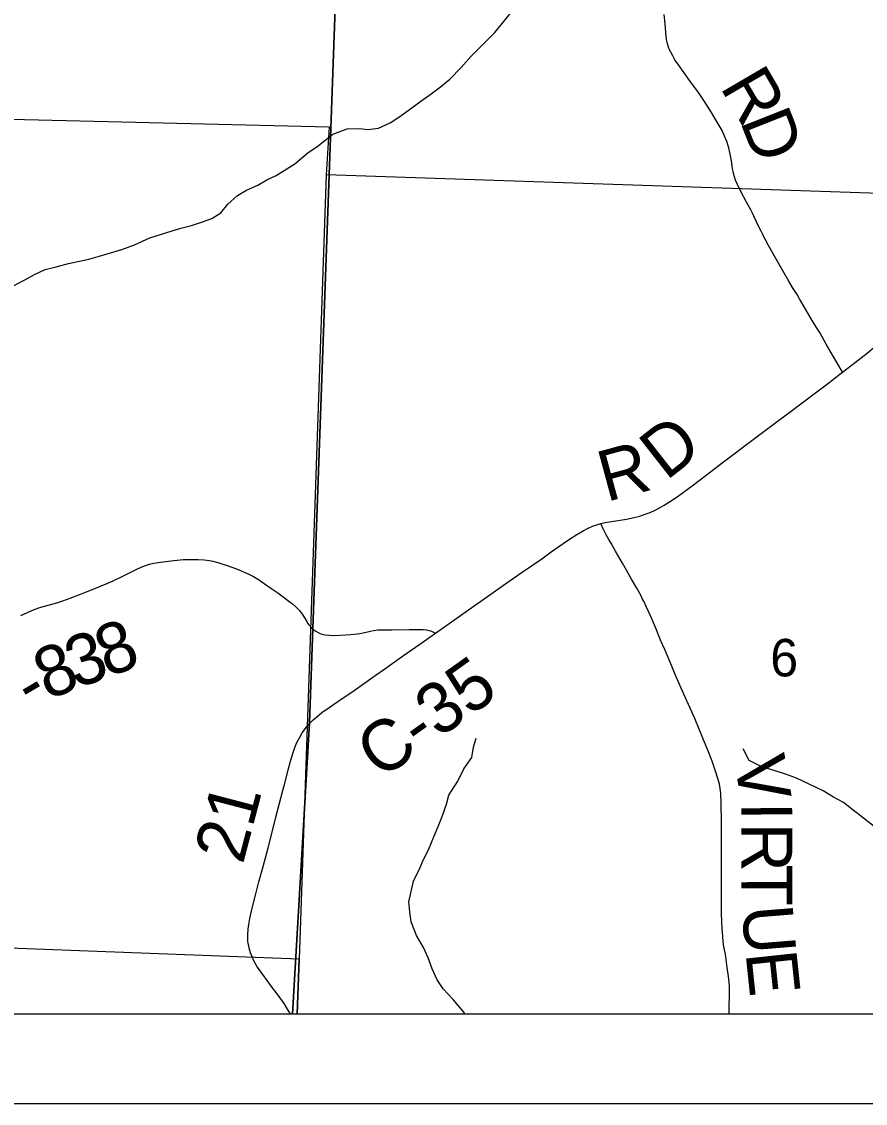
# Model space of a CAD drawing. Extents: x -14196 to 143, y -6096 to 28.
# Drawn here: x 62.009 to 62.952, y 16.799 to 18.007 of the extents above; entities that cross this region are included whole.
import ezdxf

# ---------------------------------------------------------------- set-up
doc = ezdxf.new("R2010")
doc.units = 0
for name, color, linetype in [('GM_X_Corporation', 7, 'Continuous'), ('GM_X_County_Road', 7, 'Continuous'), ('GM_X_County_Road_Text', 7, 'Continuous'), ('GM_X_Minor_River', 7, 'Continuous'), ('GM_X_Section_Text', 7, 'Continuous'), ('GM_X_Township_Road', 7, 'Continuous'), ('GM_X_Township_Road_Text', 7, 'Continuous'), ('SH_Data', 7, 'Continuous')]:
    doc.layers.add(name, color=color, linetype=linetype)

msp = doc.modelspace()

# ---------------------------------------------------------------- linework, layer by layer
at = {"layer": 'GM_X_Corporation'}
for points in [[(58.1028, 16.8985), (62.3117, 16.8985), (62.3309, 17.2239), (62.3347, 17.3291), (62.3753, 18.4575)], [(62.3753, 18.4575), (62.3347, 17.3291), (62.3309, 17.2239), (62.3117, 16.8985), (64.9028, 16.8985)], [(58.1028, 16.8985), (64.9028, 16.8985)]]:
    msp.add_lwpolyline(points, dxfattribs=at)
for points in [[(62.3528, 17.8898), (62.3495, 17.8363), (62.3192, 16.9598), (61.7888, 16.9797), (61.3, 16.9769), (61.3312, 17.9144)], [(62.3171, 16.8985), (63.3498, 16.8985), (63.3993, 17.801), (62.3495, 17.8363), (62.3192, 16.9598)], [(61.2982, 16.8985), (62.3171, 16.8985), (62.3192, 16.9598), (61.7888, 16.9797), (61.3, 16.9769)]]:
    msp.add_lwpolyline(points, close=True, dxfattribs=at)
at = {"layer": 'GM_X_County_Road'}
for points in [[(62.9266, 17.6158), (62.9412, 17.627), (62.9539, 17.6369), (62.962, 17.6437), (62.9685, 17.6497), (62.9741, 17.6555), (62.979, 17.6612), (62.9834, 17.6673), (62.987, 17.6732), (62.9901, 17.6794), (62.9922, 17.6842)], [(62.6563, 17.4465), (62.6614, 17.4476), (62.6708, 17.4493), (62.6852, 17.4516), (62.6938, 17.4532), (62.6999, 17.4549), (62.706, 17.4569), (62.7115, 17.459), (62.7171, 17.4616), (62.722, 17.4642), (62.7272, 17.4672), (62.7362, 17.4728), (62.7434, 17.4777), (62.7585, 17.4887), (62.7742, 17.5008), (62.7921, 17.5143), (62.8283, 17.5416), (62.8417, 17.5516), (62.8566, 17.5629), (62.869, 17.5722), (62.8799, 17.5804), (62.8992, 17.595), (62.9111, 17.604), (62.9234, 17.6134), (62.9266, 17.6158)], [(62.4715, 17.324), (62.4958, 17.3411), (62.5187, 17.3571), (62.5298, 17.365), (62.5476, 17.3776), (62.5675, 17.3914), (62.5905, 17.4073), (62.6011, 17.4148), (62.6204, 17.4284), (62.6298, 17.4344), (62.6367, 17.4385), (62.6422, 17.4413), (62.6471, 17.4435), (62.6518, 17.4452), (62.6563, 17.4465)], [(62.3311, 17.2233), (62.3323, 17.2246), (62.3349, 17.227), (62.339, 17.2306), (62.3448, 17.2352), (62.3539, 17.2417), (62.3662, 17.2501), (62.378, 17.2582), (62.4044, 17.2768), (62.4151, 17.2843), (62.4348, 17.2983), (62.4541, 17.3119), (62.4715, 17.324)], [(62.3096, 16.8985), (62.309, 16.8997), (62.3064, 16.9039), (62.3024, 16.9102), (62.2959, 16.9194), (62.2872, 16.9307), (62.2749, 16.9476), (62.2723, 16.9513), (62.2687, 16.9578), (62.267, 16.9617), (62.265, 16.9668), (62.2642, 16.9695), (62.2636, 16.9719), (62.263, 16.9745), (62.2624, 16.9773), (62.2621, 16.98), (62.2619, 16.9824), (62.2619, 16.9848), (62.262, 16.9873), (62.2624, 16.9934), (62.263, 16.9983), (62.264, 17.005), (62.2663, 17.0152), (62.2704, 17.0313), (62.2744, 17.0463), (62.2789, 17.0631), (62.2846, 17.0841), (62.2882, 17.0986), (62.2933, 17.1184), (62.3015, 17.1496), (62.3032, 17.1562), (62.3071, 17.1712), (62.3095, 17.1808), (62.3121, 17.1897), (62.3143, 17.1961), (62.3167, 17.2018), (62.3195, 17.2072), (62.3227, 17.2125), (62.3263, 17.2174), (62.3283, 17.22), (62.3302, 17.2223), (62.3311, 17.2233)]]:
    msp.add_lwpolyline(points, dxfattribs=at)
at = {"layer": 'GM_X_Minor_River'}
for points in [[(61.9984, 17.7113), (62.0127, 17.719), (62.0236, 17.7248), (62.0353, 17.7305), (62.0478, 17.7333), (62.0614, 17.7372), (62.0841, 17.7422), (62.0947, 17.745), (62.1049, 17.7481), (62.1211, 17.7527), (62.1351, 17.7581), (62.1524, 17.7658), (62.1713, 17.7717), (62.1872, 17.7767), (62.1989, 17.7798), (62.2114, 17.7837), (62.2216, 17.7876), (62.2317, 17.7937), (62.2396, 17.8036), (62.2505, 17.8132), (62.2603, 17.8193), (62.2731, 17.8247), (62.2833, 17.8308), (62.2935, 17.8354), (62.3146, 17.8485), (62.3293, 17.8611), (62.339, 17.8676), (62.3571, 17.8818), (62.373, 17.8876), (62.3866, 17.888), (62.3961, 17.887), (62.4078, 17.8886), (62.421, 17.8944), (62.4308, 17.9009), (62.4413, 17.9081), (62.4526, 17.9169), (62.4669, 17.9269), (62.4771, 17.9346), (62.4876, 17.9433), (62.5004, 17.9563), (62.5117, 17.9689), (62.5233, 17.9808), (62.5379, 17.9953), (62.5481, 18.0075), (62.5556, 18.017)], [(62.5045, 16.8985), (62.5032, 16.9004), (62.4913, 16.9147), (62.4802, 16.9267), (62.4737, 16.9365), (62.4679, 16.9489), (62.4633, 16.961), (62.4583, 16.9727), (62.4506, 16.9862), (62.4444, 17.0013), (62.4428, 17.0126), (62.4419, 17.0236), (62.447, 17.0467), (62.4541, 17.0615), (62.4582, 17.0709), (62.4638, 17.082), (62.4705, 17.0983), (62.4745, 17.1081), (62.479, 17.1191), (62.4838, 17.1328), (62.4867, 17.143), (62.4968, 17.1586), (62.5035, 17.1726), (62.5121, 17.1852), (62.5143, 17.1965), (62.5172, 17.2068)], [(62.9775, 17.0956), (62.9501, 17.1173), (62.9383, 17.1263), (62.9276, 17.1349), (62.9166, 17.1409), (62.9048, 17.148), (62.8892, 17.1551), (62.8751, 17.1618), (62.863, 17.1666), (62.85, 17.1706), (62.8364, 17.1747), (62.8223, 17.1818), (62.8154, 17.1946)]]:
    msp.add_lwpolyline(points, dxfattribs=at)
at = {"layer": 'GM_X_Township_Road'}
for points in [[(62.9266, 17.6158), (62.9249, 17.6185), (62.9197, 17.6272), (62.9159, 17.6336), (62.9082, 17.647), (62.901, 17.66), (62.8974, 17.6658), (62.8939, 17.6716), (62.8785, 17.6978), (62.8757, 17.7026), (62.8706, 17.7104), (62.8664, 17.7173), (62.8609, 17.727), (62.8521, 17.7427), (62.8439, 17.7573), (62.84, 17.7644), (62.8386, 17.7671), (62.837, 17.7705), (62.8356, 17.7733), (62.8331, 17.7783), (62.8277, 17.7894), (62.8258, 17.7933), (62.8247, 17.7955), (62.8239, 17.7972), (62.8208, 17.8031), (62.8194, 17.8056), (62.8128, 17.8177), (62.809, 17.8254), (62.8069, 17.8304), (62.8058, 17.8339), (62.8047, 17.838), (62.8037, 17.8435), (62.8024, 17.852), (62.8011, 17.8593), (62.7993, 17.8666), (62.7971, 17.8737), (62.7948, 17.8795), (62.7919, 17.8857), (62.7877, 17.8933), (62.78, 17.9061), (62.7724, 17.9181), (62.7654, 17.9284), (62.756, 17.9415), (62.7432, 17.9591), (62.7393, 17.9647), (62.7369, 17.9691), (62.7345, 17.9734), (62.7331, 17.9761), (62.7319, 17.979), (62.7309, 17.9826), (62.73, 17.9874), (62.7291, 17.9954), (62.7283, 18.0052), (62.7271, 18.0156)], [(62.6563, 17.4465), (62.6614, 17.4476), (62.6708, 17.4493), (62.6852, 17.4516), (62.6938, 17.4532), (62.6999, 17.4549), (62.706, 17.4569), (62.7115, 17.459), (62.7171, 17.4616), (62.722, 17.4642), (62.7272, 17.4672), (62.7362, 17.4728), (62.7434, 17.4777), (62.7585, 17.4887), (62.7742, 17.5008), (62.7921, 17.5143), (62.8283, 17.5416), (62.8417, 17.5516), (62.8566, 17.5629), (62.869, 17.5722), (62.8799, 17.5804), (62.8992, 17.595), (62.9111, 17.604), (62.9234, 17.6134), (62.9266, 17.6158)], [(62.8, 16.8985), (62.8, 16.9029), (62.8003, 16.9236), (62.8001, 16.9288), (62.7997, 16.9341), (62.7991, 16.9403), (62.7977, 16.9502), (62.7956, 16.9651), (62.794, 16.9734), (62.7932, 16.979), (62.7926, 16.9854), (62.792, 16.9941), (62.7914, 17.0102), (62.7912, 17.0306), (62.7912, 17.038), (62.7912, 17.0454), (62.7912, 17.0631), (62.7913, 17.0786), (62.7913, 17.0949), (62.7913, 17.1125), (62.7909, 17.1341), (62.7904, 17.1447), (62.7898, 17.1504), (62.7889, 17.1551), (62.7873, 17.1617), (62.7851, 17.1688), (62.7808, 17.181), (62.776, 17.1931), (62.7713, 17.2047), (62.7614, 17.2288), (62.7563, 17.2401), (62.7492, 17.256), (62.7407, 17.2753), (62.7346, 17.2896), (62.7278, 17.3056), (62.7233, 17.3164), (62.7185, 17.3278), (62.7123, 17.3427), (62.7072, 17.354), (62.7048, 17.359), (62.7028, 17.3629), (62.7014, 17.3656), (62.6966, 17.3743), (62.6907, 17.3845), (62.6855, 17.3937), (62.6805, 17.4023), (62.6728, 17.4157), (62.6682, 17.4238), (62.6655, 17.4287), (62.6624, 17.4341), (62.6591, 17.4407), (62.6563, 17.4465)], [(62.0083, 17.3437), (62.0157, 17.347), (62.0233, 17.3504), (62.0305, 17.3531), (62.0486, 17.3581), (62.0551, 17.3603), (62.0633, 17.3632), (62.0749, 17.3676), (62.0807, 17.3698), (62.0911, 17.3739), (62.1037, 17.3791), (62.1116, 17.3827), (62.1222, 17.3876), (62.1305, 17.3918), (62.1372, 17.3951), (62.1427, 17.3977), (62.1475, 17.3995), (62.1519, 17.401), (62.1568, 17.4021), (62.1642, 17.4033), (62.1794, 17.4052), (62.1899, 17.4062), (62.1984, 17.4065), (62.2063, 17.4065), (62.2133, 17.406), (62.2191, 17.4054), (62.223, 17.4046), (62.2285, 17.4032), (62.2389, 17.3998), (62.2492, 17.3959), (62.263, 17.39), (62.2676, 17.3878), (62.2739, 17.3839), (62.2828, 17.3778), (62.2888, 17.3736), (62.2955, 17.369), (62.3029, 17.3637), (62.3079, 17.3599), (62.3117, 17.3569), (62.3158, 17.3531), (62.3184, 17.3506), (62.3196, 17.3492), (62.3211, 17.3473), (62.3229, 17.3448), (62.3252, 17.3412), (62.3277, 17.3369), (62.3287, 17.3352), (62.3301, 17.3334), (62.3312, 17.3322), (62.3332, 17.33), (62.3349, 17.3285)], [(62.3349, 17.3285), (62.3356, 17.3279), (62.3381, 17.3262), (62.3405, 17.3248), (62.3427, 17.3238), (62.3448, 17.3231), (62.3466, 17.3226), (62.3485, 17.3223), (62.3529, 17.3218), (62.3578, 17.3216), (62.3715, 17.3222), (62.377, 17.3225), (62.3842, 17.3232), (62.3871, 17.3236), (62.391, 17.3243), (62.3991, 17.3262), (62.4023, 17.327), (62.4048, 17.3274), (62.4072, 17.3277), (62.4099, 17.3278), (62.4231, 17.3278), (62.4423, 17.3281), (62.454, 17.3282), (62.4578, 17.328), (62.4616, 17.3277), (62.4643, 17.3272), (62.4665, 17.3266), (62.4681, 17.326), (62.4715, 17.324)]]:
    msp.add_lwpolyline(points, dxfattribs=at)
at = {"layer": 'SH_Data'}
for p, q in [((58.1028, 16.8985), (64.9028, 16.8985)), ((58.0028, 16.7985), (65.0028, 16.7985))]:
    msp.add_line(p, q, dxfattribs=at)

# ---------------------------------------------------------------- texts
at = {"layer": 'GM_X_County_Road_Text'}
for s, height, rotation, p in [('D', 0.0568, 38.1431, (62.7294, 17.4937)), ('R', 0.0568, 15.1723, (62.6626, 17.4705)), ('C-35', 0.05682, 35.5374, (62.4103, 17.1595)), ('21', 0.05682, 75.2914, (62.2563, 17.0647))]:
    msp.add_text(s, height=height, rotation=rotation, dxfattribs=at).set_placement(p)
at = {"layer": 'GM_X_Section_Text'}
msp.add_text('6', height=0.0419, rotation=0, dxfattribs=at).set_placement((62.8458, 17.2757))
at = {"layer": 'GM_X_Township_Road_Text'}
for s, rotation, p in [('R', 300.2837, (62.789, 17.9347)), ('D', 291.5802, (62.8116, 17.8964)), ('8', 21.0905, (62.1051, 17.274)), ('3', 18.7163, (62.0696, 17.2619)), ('8', 23.2956, (62.0385, 17.2485)), ('-', 30.6037, (62.0202, 17.2375)), ('V', 279.6923, (62.8052, 17.1822)), ('I', 270.4371, (62.8134, 17.1353)), ('R', 270.0195, (62.8136, 17.1121)), ('T', 270.0671, (62.8136, 17.0654)), ('U', 274.6745, (62.8139, 17.018)), ('E', 276.0747, (62.8181, 16.9666))]:
    msp.add_text(s, height=0.0568, rotation=rotation, dxfattribs=at).set_placement(p)

doc.saveas('drawing.dxf')
